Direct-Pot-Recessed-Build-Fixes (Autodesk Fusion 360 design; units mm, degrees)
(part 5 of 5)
sketch "Top installation slot for block nut (2)" plane through (-20, 0, 0) normal (1, 0, 0) x axis (0, 0, -1)
  line L1 (-53.5, -66.65) -> (-53.5, -73.35)
  line L2 (-59.1, -66.65) -> (-53.5, -66.65)
  line L3 (-59.1, -73.35) -> (-59.1, -66.65)
  line L4 (-53.5, -73.35) -> (-59.1, -73.35)
extrude "Extrude80" cut sketch "Top installation slot for block nut (2)" along normal blind 2.6
work_plane "WorkPlane1" AlongDistance -19.9 ExtraOffset 0
sketch "Crossblock captive M3 (-70, -1)" plane through (-19.9, 0, 0) normal (1, 0, 0) x axis (0, 0, -1)
  line L1 (-56.25, -68.4123) -> (-53.5, -66.8246)
  line L2 (-56.25, -71.5877) -> (-56.25, -68.4123)
  line L3 (-53.5, -73.1754) -> (-56.25, -71.5877)
  line L4 (-50.75, -71.5877) -> (-53.5, -73.1754)
  line L5 (-50.75, -68.4123) -> (-50.75, -71.5877)
  line L6 (-53.5, -66.8246) -> (-50.75, -68.4123)
extrude "Extrude1" new body sketch "Crossblock captive M3 (-70, -1)" along normal blind 2.4 bodies "HARDWARE Crossblock captive M3 (-70, -1)"
work_plane "WorkPlane2" AlongDistance -20 ExtraOffset 0
sketch "Thread envelope" plane through (-20, 0, 0) normal (1, 0, 0) x axis (0, 0, -1)
  circle C1 centre (-53.5, -70) radius 1.5
extrude "Extrude2" cut sketch "Thread envelope" along normal blind 2.6
work_plane "WorkPlane81" AlongDistance 15.3 ExtraOffset 0
sketch "Close mounting insert pilot (3)" plane through (15.3, 0, 0) normal (1, 0, 0) x axis (0, 0, -1)
  circle C1 centre (-53.5, -70) radius 2.01
extrude "Extrude81" add sketch "Close mounting insert pilot (3)" along normal blind 8.7
work_plane "WorkPlane82" AlongDistance 15.2 ExtraOffset 0
sketch "Block mount screw passage (3)" plane through (15.2, 0, 0) normal (1, 0, 0) x axis (0, 0, -1)
  circle C1 centre (-53.5, -70) radius 1.7
extrude "Extrude82" cut sketch "Block mount screw passage (3)" along normal blind 8.9
work_plane "WorkPlane83" AlongDistance 17.4 ExtraOffset 0
sketch "Crossblock captive hex nut (3)" plane through (17.4, 0, 0) normal (1, 0, 0) x axis (0, 0, -1)
  line L1 (-56.4, -68.3257) -> (-53.5, -66.6514)
  line L2 (-56.4, -71.6743) -> (-56.4, -68.3257)
  line L3 (-53.5, -73.3486) -> (-56.4, -71.6743)
  line L4 (-50.6, -71.6743) -> (-53.5, -73.3486)
  line L5 (-50.6, -68.3257) -> (-50.6, -71.6743)
  line L6 (-53.5, -66.6514) -> (-50.6, -68.3257)
extrude "Extrude83" cut sketch "Crossblock captive hex nut (3)" along normal blind 2.6
work_plane "WorkPlane84" AlongDistance 17.4 ExtraOffset 0
sketch "Top installation slot for block nut (3)" plane through (17.4, 0, 0) normal (1, 0, 0) x axis (0, 0, -1)
  line L1 (-53.5, -66.65) -> (-53.5, -73.35)
  line L2 (-59.1, -66.65) -> (-53.5, -66.65)
  line L3 (-59.1, -73.35) -> (-59.1, -66.65)
  line L4 (-53.5, -73.35) -> (-59.1, -73.35)
extrude "Extrude84" cut sketch "Top installation slot for block nut (3)" along normal blind 2.6
work_plane "WorkPlane1" AlongDistance 17.5 ExtraOffset 0
sketch "Crossblock captive M3 (-70, 1)" plane through (17.5, 0, 0) normal (1, 0, 0) x axis (0, 0, -1)
  line L1 (-56.25, -68.4123) -> (-53.5, -66.8246)
  line L2 (-56.25, -71.5877) -> (-56.25, -68.4123)
  line L3 (-53.5, -73.1754) -> (-56.25, -71.5877)
  line L4 (-50.75, -71.5877) -> (-53.5, -73.1754)
  line L5 (-50.75, -68.4123) -> (-50.75, -71.5877)
  line L6 (-53.5, -66.8246) -> (-50.75, -68.4123)
extrude "Extrude1" new body sketch "Crossblock captive M3 (-70, 1)" along normal blind 2.4 bodies "HARDWARE Crossblock captive M3 (-70, 1)"
work_plane "WorkPlane2" AlongDistance 17.4 ExtraOffset 0
sketch "Thread envelope" plane through (17.4, 0, 0) normal (1, 0, 0) x axis (0, 0, -1)
  circle C1 centre (-53.5, -70) radius 1.5
extrude "Extrude2" cut sketch "Thread envelope" along normal blind 2.6
work_plane "WorkPlane85" AlongDistance 8.6 ExtraOffset 0
sketch "Preload head first bridge relief" plane through (8.6, 0, 0) normal (1, 0, 0) x axis (0, 0, -1)
  line L1 (-54.8, -53.3) -> (-54.8, -56.7)
  line L2 (-55, -53.3) -> (-54.8, -53.3)
  line L3 (-55, -56.7) -> (-55, -53.3)
  line L4 (-54.8, -56.7) -> (-55, -56.7)
extrude "Extrude85" cut sketch "Preload head first bridge relief" along normal blind 6.8
work_plane "WorkPlane86" AlongDistance 10.3 ExtraOffset 0
sketch "Preload head crossed bridge relief" plane through (10.3, 0, 0) normal (1, 0, 0) x axis (0, 0, -1)
  line L1 (-54.6, -53.3) -> (-54.6, -56.7)
  line L2 (-54.8, -53.3) -> (-54.6, -53.3)
  line L3 (-54.8, -56.7) -> (-54.8, -53.3)
  line L4 (-54.6, -56.7) -> (-54.8, -56.7)
extrude "Extrude86" cut sketch "Preload head crossed bridge relief" along normal blind 3.4
work_plane "WorkPlane9" AlongDistance -9 ExtraOffset 0
sketch "Close sensor clamp insert pilot" plane through (0, -9, 0) normal (0, 1, 0) x axis (1, 0, 0)
  circle C1 centre (54.15, -73) radius 2.01
extrude "Extrude9" add sketch "Close sensor clamp insert pilot" along normal blind 8.9
work_plane "WorkPlane10" AlongDistance -9.1 ExtraOffset 0
sketch "Sensor clamp M3 clearance" plane through (0, -9.1, 0) normal (0, 1, 0) x axis (1, 0, 0)
  circle C1 centre (54.15, -73) radius 1.7
extrude "Extrude10" cut sketch "Sensor clamp M3 clearance" along normal blind 9.1
work_plane "WorkPlane11" AlongDistance -6.9 ExtraOffset 0
sketch "Sensor clamp captive hex nut" plane through (0, -6.9, 0) normal (0, 1, 0) x axis (1, 0, 0)
  line L1 (55.8243, -75.9) -> (57.4986, -73)
  line L2 (52.4757, -75.9) -> (55.8243, -75.9)
  line L3 (50.8014, -73) -> (52.4757, -75.9)
  line L4 (52.4757, -70.1) -> (50.8014, -73)
  line L5 (55.8243, -70.1) -> (52.4757, -70.1)
  line L6 (57.4986, -73) -> (55.8243, -70.1)
extrude "Extrude11" cut sketch "Sensor clamp captive hex nut" along normal blind 2.6
work_plane "WorkPlane12" AlongDistance 50.8 ExtraOffset 0
sketch "Clamp nut top installation slot" plane through (50.8, 0, 0) normal (1, 0, 0) x axis (0, 0, -1)
  line L1 (-73, -4.3) -> (-73, -6.9)
  line L2 (-78.1, -4.3) -> (-73, -4.3)
  line L3 (-78.1, -6.9) -> (-78.1, -4.3)
  line L4 (-73, -6.9) -> (-78.1, -6.9)
extrude "Extrude12" cut sketch "Clamp nut top installation slot" along normal blind 6.7
work_plane "WorkPlane1" AlongDistance -6.8 ExtraOffset 0
sketch "Sensor clamp captive M3 nut" plane through (0, -6.8, 0) normal (0, 1, 0) x axis (1, 0, 0)
  line L1 (55.7377, -75.75) -> (57.3254, -73)
  line L2 (52.5623, -75.75) -> (55.7377, -75.75)
  line L3 (50.9746, -73) -> (52.5623, -75.75)
  line L4 (52.5623, -70.25) -> (50.9746, -73)
  line L5 (55.7377, -70.25) -> (52.5623, -70.25)
  line L6 (57.3254, -73) -> (55.7377, -70.25)
extrude "Extrude1" new body sketch "Sensor clamp captive M3 nut" along normal blind 2.4 bodies "HARDWARE Sensor clamp captive M3 nut"
work_plane "WorkPlane2" AlongDistance -6.9 ExtraOffset 0
sketch "Thread envelope" plane through (0, -6.9, 0) normal (0, 1, 0) x axis (1, 0, 0)
  circle C1 centre (54.15, -73) radius 1.5
extrude "Extrude2" cut sketch "Thread envelope" along normal blind 2.6
work_plane "WorkPlane87" AlongDistance -24 ExtraOffset 0
sketch "Rear wall around captive block nuts" plane through (-24, 0, 0) normal (1, 0, 0) x axis (0, 0, -1)
  line L1 (-38, -73.9) -> (-38, -76)
  line L2 (-59, -73.9) -> (-38, -73.9)
  line L3 (-59, -76) -> (-59, -73.9)
  line L4 (-38, -76) -> (-59, -76)
extrude "Extrude87" add sketch "Rear wall around captive block nuts" along normal blind 48
work_plane "WorkPlane88" AlongDistance 1.1 ExtraOffset 0
sketch "Extend guide nut loading access through rear wall" plane through (1.1, 0, 0) normal (1, 0, 0) x axis (0, 0, -1)
  line L1 (-40.8, -73.8) -> (-40.8, -76.1)
  line L2 (-43.4, -73.8) -> (-40.8, -73.8)
  line L3 (-43.4, -76.1) -> (-43.4, -73.8)
  line L4 (-40.8, -76.1) -> (-43.4, -76.1)
extrude "Extrude88" cut sketch "Extend guide nut loading access through rear wall" along normal blind 5.8
work_plane "WorkPlane89" AlongDistance 17.1 ExtraOffset 0
sketch "Extend guide nut loading access through rear wall (1)" plane through (17.1, 0, 0) normal (1, 0, 0) x axis (0, 0, -1)
  line L1 (-40.8, -73.8) -> (-40.8, -76.1)
  line L2 (-43.4, -73.8) -> (-40.8, -73.8)
  line L3 (-43.4, -76.1) -> (-43.4, -73.8)
  line L4 (-40.8, -76.1) -> (-43.4, -76.1)
extrude "Extrude89" cut sketch "Extend guide nut loading access through rear wall (1)" along normal blind 5.8
work_plane "WorkPlane19" AlongDistance -34 ExtraOffset 0
sketch "Shaft cap nut captured by assembled halves" plane through (-34, 0, 0) normal (1, 0, 0) x axis (0, 0, -1)
  line L1 (-67.9, 1.6743) -> (-65, 3.3486)
  line L2 (-67.9, -1.6743) -> (-67.9, 1.6743)
  line L3 (-65, -3.3486) -> (-67.9, -1.6743)
  line L4 (-62.1, -1.6743) -> (-65, -3.3486)
  line L5 (-62.1, 1.6743) -> (-62.1, -1.6743)
  line L6 (-65, 3.3486) -> (-62.1, 1.6743)
extrude "Extrude19" cut sketch "Shaft cap nut captured by assembled halves" along normal blind 2.6
work_plane "WorkPlane1" AlongDistance -33.9 ExtraOffset 0
sketch "Shaft cap captured M3 nut" plane through (-33.9, 0, 0) normal (1, 0, 0) x axis (0, 0, -1)
  line L1 (-67.75, 1.5877) -> (-65, 3.1754)
  line L2 (-67.75, -1.5877) -> (-67.75, 1.5877)
  line L3 (-65, -3.1754) -> (-67.75, -1.5877)
  line L4 (-62.25, -1.5877) -> (-65, -3.1754)
  line L5 (-62.25, 1.5877) -> (-62.25, -1.5877)
  line L6 (-65, 3.1754) -> (-62.25, 1.5877)
extrude "Extrude1" new body sketch "Shaft cap captured M3 nut" along normal blind 2.4 bodies "HARDWARE Shaft cap captured M3 nut"
work_plane "WorkPlane2" AlongDistance -34 ExtraOffset 0
sketch "Thread envelope" plane through (-34, 0, 0) normal (1, 0, 0) x axis (0, 0, -1)
  circle C1 centre (-65, 0) radius 1.5
extrude "Extrude2" cut sketch "Thread envelope" along normal blind 2.6
work_plane "WorkPlane20" AlongDistance -4.5 ExtraOffset 0
sketch "Shaft joining captured nut" plane through (0, -4.5, 0) normal (0, 1, 0) x axis (1, 0, 0)
  line L1 (-13.3257, -67.9) -> (-11.6514, -65)
  line L2 (-16.6743, -67.9) -> (-13.3257, -67.9)
  line L3 (-18.3486, -65) -> (-16.6743, -67.9)
  line L4 (-16.6743, -62.1) -> (-18.3486, -65)
  line L5 (-13.3257, -62.1) -> (-16.6743, -62.1)
  line L6 (-11.6514, -65) -> (-13.3257, -62.1)
extrude "Extrude20" cut sketch "Shaft joining captured nut" along normal blind 2.6
work_plane "WorkPlane21" AlongDistance -18.35 ExtraOffset 0
sketch "Shaft nut loading slot from underside" plane through (-18.35, 0, 0) normal (1, 0, 0) x axis (0, 0, -1)
  line L1 (-56.9, -1.9) -> (-56.9, -4.5)
  line L2 (-65, -1.9) -> (-56.9, -1.9)
  line L3 (-65, -4.5) -> (-65, -1.9)
  line L4 (-56.9, -4.5) -> (-65, -4.5)
extrude "Extrude21" cut sketch "Shaft nut loading slot from underside" along normal blind 6.7
work_plane "WorkPlane22" AlongDistance -18.35 ExtraOffset 0
sketch "Shaft nut first anchored bridge relief" plane through (-18.35, 0, 0) normal (1, 0, 0) x axis (0, 0, -1)
  line L1 (-63.3, -4.5) -> (-63.3, -4.7)
  line L2 (-66.7, -4.5) -> (-63.3, -4.5)
  line L3 (-66.7, -4.7) -> (-66.7, -4.5)
  line L4 (-63.3, -4.7) -> (-66.7, -4.7)
extrude "Extrude22" cut sketch "Shaft nut first anchored bridge relief" along normal blind 6.7
work_plane "WorkPlane23" AlongDistance -16.7 ExtraOffset 0
sketch "Shaft nut crossed bridge relief" plane through (-16.7, 0, 0) normal (1, 0, 0) x axis (0, 0, -1)
  line L1 (-63.3, -4.7) -> (-63.3, -4.9)
  line L2 (-66.7, -4.7) -> (-63.3, -4.7)
  line L3 (-66.7, -4.9) -> (-66.7, -4.7)
  line L4 (-63.3, -4.9) -> (-66.7, -4.9)
extrude "Extrude23" cut sketch "Shaft nut crossed bridge relief" along normal blind 3.4
work_plane "WorkPlane1" AlongDistance -4.4 ExtraOffset 0
sketch "Shaft joining captured M3 nut -15" plane through (0, -4.4, 0) normal (0, 1, 0) x axis (1, 0, 0)
  line L1 (-13.4123, -67.75) -> (-11.8246, -65)
  line L2 (-16.5877, -67.75) -> (-13.4123, -67.75)
  line L3 (-18.1754, -65) -> (-16.5877, -67.75)
  line L4 (-16.5877, -62.25) -> (-18.1754, -65)
  line L5 (-13.4123, -62.25) -> (-16.5877, -62.25)
  line L6 (-11.8246, -65) -> (-13.4123, -62.25)
extrude "Extrude1" new body sketch "Shaft joining captured M3 nut -15" along normal blind 2.4 bodies "HARDWARE Shaft joining captured M3 nut -15"
work_plane "WorkPlane2" AlongDistance -4.5 ExtraOffset 0
sketch "Thread envelope" plane through (0, -4.5, 0) normal (0, 1, 0) x axis (1, 0, 0)
  circle C1 centre (-15, -65) radius 1.5
extrude "Extrude2" cut sketch "Thread envelope" along normal blind 2.6
work_plane "WorkPlane24" AlongDistance -4.5 ExtraOffset 0
sketch "Shaft joining captured nut (1)" plane through (0, -4.5, 0) normal (0, 1, 0) x axis (1, 0, 0)
  line L1 (16.6743, -67.9) -> (18.3486, -65)
  line L2 (13.3257, -67.9) -> (16.6743, -67.9)
  line L3 (11.6514, -65) -> (13.3257, -67.9)
  line L4 (13.3257, -62.1) -> (11.6514, -65)
  line L5 (16.6743, -62.1) -> (13.3257, -62.1)
  line L6 (18.3486, -65) -> (16.6743, -62.1)
extrude "Extrude24" cut sketch "Shaft joining captured nut (1)" along normal blind 2.6
work_plane "WorkPlane25" AlongDistance 11.65 ExtraOffset 0
sketch "Shaft nut loading slot from underside (1)" plane through (11.65, 0, 0) normal (1, 0, 0) x axis (0, 0, -1)
  line L1 (-56.9, -1.9) -> (-56.9, -4.5)
  line L2 (-65, -1.9) -> (-56.9, -1.9)
  line L3 (-65, -4.5) -> (-65, -1.9)
  line L4 (-56.9, -4.5) -> (-65, -4.5)
extrude "Extrude25" cut sketch "Shaft nut loading slot from underside (1)" along normal blind 6.7
work_plane "WorkPlane26" AlongDistance 11.65 ExtraOffset 0
sketch "Shaft nut first anchored bridge relief (1)" plane through (11.65, 0, 0) normal (1, 0, 0) x axis (0, 0, -1)
  line L1 (-63.3, -4.5) -> (-63.3, -4.7)
  line L2 (-66.7, -4.5) -> (-63.3, -4.5)
  line L3 (-66.7, -4.7) -> (-66.7, -4.5)
  line L4 (-63.3, -4.7) -> (-66.7, -4.7)
extrude "Extrude26" cut sketch "Shaft nut first anchored bridge relief (1)" along normal blind 6.7
work_plane "WorkPlane27" AlongDistance 13.3 ExtraOffset 0
sketch "Shaft nut crossed bridge relief (1)" plane through (13.3, 0, 0) normal (1, 0, 0) x axis (0, 0, -1)
  line L1 (-63.3, -4.7) -> (-63.3, -4.9)
  line L2 (-66.7, -4.7) -> (-63.3, -4.7)
  line L3 (-66.7, -4.9) -> (-66.7, -4.7)
  line L4 (-63.3, -4.9) -> (-66.7, -4.9)
extrude "Extrude27" cut sketch "Shaft nut crossed bridge relief (1)" along normal blind 3.4
work_plane "WorkPlane1" AlongDistance -4.4 ExtraOffset 0
sketch "Shaft joining captured M3 nut 15" plane through (0, -4.4, 0) normal (0, 1, 0) x axis (1, 0, 0)
  line L1 (16.5877, -67.75) -> (18.1754, -65)
  line L2 (13.4123, -67.75) -> (16.5877, -67.75)
  line L3 (11.8246, -65) -> (13.4123, -67.75)
  line L4 (13.4123, -62.25) -> (11.8246, -65)
  line L5 (16.5877, -62.25) -> (13.4123, -62.25)
  line L6 (18.1754, -65) -> (16.5877, -62.25)
extrude "Extrude1" new body sketch "Shaft joining captured M3 nut 15" along normal blind 2.4 bodies "HARDWARE Shaft joining captured M3 nut 15"
work_plane "WorkPlane2" AlongDistance -4.5 ExtraOffset 0
sketch "Thread envelope" plane through (0, -4.5, 0) normal (0, 1, 0) x axis (1, 0, 0)
  circle C1 centre (15, -65) radius 1.5
extrude "Extrude2" cut sketch "Thread envelope" along normal blind 2.6
work_plane "WorkPlane21" AlongDistance -7.1 ExtraOffset 0
sketch "Rear-loaded cam hex nut" plane through (-7.1, 0, 0) normal (1, 0, 0) x axis (0, 0, -1)
  line L1 (-42.4442, 27.1302) -> (-39.5442, 28.8045)
  line L2 (-42.4442, 23.7815) -> (-42.4442, 27.1302)
  line L3 (-39.5442, 22.1072) -> (-42.4442, 23.7815)
  line L4 (-36.6442, 23.7815) -> (-39.5442, 22.1072)
  line L5 (-36.6442, 27.1302) -> (-36.6442, 23.7815)
  line L6 (-39.5442, 28.8045) -> (-36.6442, 27.1302)
extrude "Extrude21" cut sketch "Rear-loaded cam hex nut" along normal blind 11.7
work_plane "WorkPlane1" AlongDistance 2.1 ExtraOffset 0
sketch "Cam captured M3 nut -45" plane through (2.1, 0, 0) normal (1, 0, 0) x axis (0, 0, -1)
  line L1 (-42.2942, 27.0436) -> (-39.5442, 28.6313)
  line L2 (-42.2942, 23.8681) -> (-42.2942, 27.0436)
  line L3 (-39.5442, 22.2804) -> (-42.2942, 23.8681)
  line L4 (-36.7942, 23.8681) -> (-39.5442, 22.2804)
  line L5 (-36.7942, 27.0436) -> (-36.7942, 23.8681)
  line L6 (-39.5442, 28.6313) -> (-36.7942, 27.0436)
extrude "Extrude1" new body sketch "Cam captured M3 nut -45" along normal blind 2.4 bodies "HARDWARE Cam captured M3 nut -45"
work_plane "WorkPlane2" AlongDistance 2 ExtraOffset 0
sketch "Thread envelope" plane through (2, 0, 0) normal (1, 0, 0) x axis (0, 0, -1)
  circle C1 centre (-39.5442, 25.4558) radius 1.5
extrude "Extrude2" cut sketch "Thread envelope" along normal blind 2.6
work_plane "WorkPlane22" AlongDistance -7.1 ExtraOffset 0
sketch "Rear-loaded cam hex nut (1)" plane through (-7.1, 0, 0) normal (1, 0, 0) x axis (0, 0, -1)
  line L1 (-31.9, 1.6743) -> (-29, 3.3486)
  line L2 (-31.9, -1.6743) -> (-31.9, 1.6743)
  line L3 (-29, -3.3486) -> (-31.9, -1.6743)
  line L4 (-26.1, -1.6743) -> (-29, -3.3486)
  line L5 (-26.1, 1.6743) -> (-26.1, -1.6743)
  line L6 (-29, 3.3486) -> (-26.1, 1.6743)
extrude "Extrude22" cut sketch "Rear-loaded cam hex nut (1)" along normal blind 11.7
work_plane "WorkPlane1" AlongDistance 2.1 ExtraOffset 0
sketch "Cam captured M3 nut 0" plane through (2.1, 0, 0) normal (1, 0, 0) x axis (0, 0, -1)
  line L1 (-31.75, 1.5877) -> (-29, 3.1754)
  line L2 (-31.75, -1.5877) -> (-31.75, 1.5877)
  line L3 (-29, -3.1754) -> (-31.75, -1.5877)
  line L4 (-26.25, -1.5877) -> (-29, -3.1754)
  line L5 (-26.25, 1.5877) -> (-26.25, -1.5877)
  line L6 (-29, 3.1754) -> (-26.25, 1.5877)
extrude "Extrude1" new body sketch "Cam captured M3 nut 0" along normal blind 2.4 bodies "HARDWARE Cam captured M3 nut 0"
work_plane "WorkPlane2" AlongDistance 2 ExtraOffset 0
sketch "Thread envelope" plane through (2, 0, 0) normal (1, 0, 0) x axis (0, 0, -1)
  circle C1 centre (-29, 0) radius 1.5
extrude "Extrude2" cut sketch "Thread envelope" along normal blind 2.6
work_plane "WorkPlane23" AlongDistance -7.1 ExtraOffset 0
sketch "Rear-loaded cam hex nut (2)" plane through (-7.1, 0, 0) normal (1, 0, 0) x axis (0, 0, -1)
  line L1 (-42.4442, -23.7815) -> (-39.5442, -22.1072)
  line L2 (-42.4442, -27.1302) -> (-42.4442, -23.7815)
  line L3 (-39.5442, -28.8045) -> (-42.4442, -27.1302)
  line L4 (-36.6442, -27.1302) -> (-39.5442, -28.8045)
  line L5 (-36.6442, -23.7815) -> (-36.6442, -27.1302)
  line L6 (-39.5442, -22.1072) -> (-36.6442, -23.7815)
extrude "Extrude23" cut sketch "Rear-loaded cam hex nut (2)" along normal blind 11.7
work_plane "WorkPlane1" AlongDistance 2.1 ExtraOffset 0
sketch "Cam captured M3 nut 45" plane through (2.1, 0, 0) normal (1, 0, 0) x axis (0, 0, -1)
  line L1 (-42.2942, -23.8681) -> (-39.5442, -22.2804)
  line L2 (-42.2942, -27.0436) -> (-42.2942, -23.8681)
  line L3 (-39.5442, -28.6313) -> (-42.2942, -27.0436)
  line L4 (-36.7942, -27.0436) -> (-39.5442, -28.6313)
  line L5 (-36.7942, -23.8681) -> (-36.7942, -27.0436)
  line L6 (-39.5442, -22.2804) -> (-36.7942, -23.8681)
extrude "Extrude1" new body sketch "Cam captured M3 nut 45" along normal blind 2.4 bodies "HARDWARE Cam captured M3 nut 45"
work_plane "WorkPlane2" AlongDistance 2 ExtraOffset 0
sketch "Thread envelope" plane through (2, 0, 0) normal (1, 0, 0) x axis (0, 0, -1)
  circle C1 centre (-39.5442, -25.4558) radius 1.5
extrude "Extrude2" cut sketch "Thread envelope" along normal blind 2.6
work_plane "WorkPlane24" AlongDistance 15.2 ExtraOffset 0
sketch "Rotor side-loaded clamp nut" plane through (0, 15.2, 0) normal (0, 1, 0) x axis (1, 0, 0)
  line L1 (1.6743, -67.9) -> (3.3486, -65)
  line L2 (-1.6743, -67.9) -> (1.6743, -67.9)
  line L3 (-3.3486, -65) -> (-1.6743, -67.9)
  line L4 (-1.6743, -62.1) -> (-3.3486, -65)
  line L5 (1.6743, -62.1) -> (-1.6743, -62.1)
  line L6 (3.3486, -65) -> (1.6743, -62.1)
extrude "Extrude24" cut sketch "Rotor side-loaded clamp nut" along normal blind 2.6
work_plane "WorkPlane25" AlongDistance -7.1 ExtraOffset 0
sketch "Rotor clamp nut insertion from back face" plane through (-7.1, 0, 0) normal (1, 0, 0) x axis (0, 0, -1)
  line L1 (-62.1, 17.8) -> (-62.1, 15.2)
  line L2 (-67.9, 17.8) -> (-62.1, 17.8)
  line L3 (-67.9, 15.2) -> (-67.9, 17.8)
  line L4 (-62.1, 15.2) -> (-67.9, 15.2)
extrude "Extrude25" cut sketch "Rotor clamp nut insertion from back face" along normal blind 7.1
work_plane "WorkPlane1" AlongDistance 15.3 ExtraOffset 0
sketch "Rotor clamp captured M3 nut" plane through (0, 15.3, 0) normal (0, 1, 0) x axis (1, 0, 0)
  line L1 (1.5877, -67.75) -> (3.1754, -65)
  line L2 (-1.5877, -67.75) -> (1.5877, -67.75)
  line L3 (-3.1754, -65) -> (-1.5877, -67.75)
  line L4 (-1.5877, -62.25) -> (-3.1754, -65)
  line L5 (1.5877, -62.25) -> (-1.5877, -62.25)
  line L6 (3.1754, -65) -> (1.5877, -62.25)
extrude "Extrude1" new body sketch "Rotor clamp captured M3 nut" along normal blind 2.4 bodies "HARDWARE Rotor clamp captured M3 nut"
work_plane "WorkPlane2" AlongDistance 15.2 ExtraOffset 0
sketch "Thread envelope" plane through (0, 15.2, 0) normal (0, 1, 0) x axis (1, 0, 0)
  circle C1 centre (0, -65) radius 1.5
extrude "Extrude2" cut sketch "Thread envelope" along normal blind 2.6
work_plane "WorkPlane7" AlongDistance 180 ExtraOffset 0
sketch "Small grip socket insert lead-in" plane through (0, 0, 180) normal (0, 0, 1) x axis (1, 0, 0)
  line L1 (-7.4, 1.9) -> (-7.4, 0)
  line L2 (-7.2, 2.1) -> (-7.4, 1.9)
  line L3 (-7.2, 0) -> (-7.2, 2.1)
  line L4 (-7.4, 0) -> (-7.2, 0)
  line L5 (-6.2, 0) -> (-8.4, 0)
revolve "Revolve2" sketch "Small grip socket insert lead-in" AlongAngle 360
work_plane "WorkPlane8" AlongDistance 190 ExtraOffset 0
sketch "Small grip socket insert lead-in (1)" plane through (0, 0, 190) normal (0, 0, 1) x axis (1, 0, 0)
  line L1 (-7.4, 1.9) -> (-7.4, 0)
  line L2 (-7.2, 2.1) -> (-7.4, 1.9)
  line L3 (-7.2, 0) -> (-7.2, 2.1)
  line L4 (-7.4, 0) -> (-7.2, 0)
  line L5 (-6.2, 0) -> (-8.4, 0)
revolve "Revolve3" sketch "Small grip socket insert lead-in (1)" AlongAngle 360
ground "Pin164"
ground "Pin165"
ground "Pin166"
ground "Pin167"
ground "Pin168"
ground "Pin169"
ground "Pin170"
ground "Pin171"
ground "Pin172"
ground "Pin173"
ground "Pin174"
ground "Pin175"
ground "Pin176"
ground "Pin177"
ground "Pin178"
ground "Pin179"
ground "Pin180"
ground "Pin181"
ground "Pin182"
ground "Pin183"
ground "Pin184"
ground "Pin185"
ground "Pin186"
ground "Pin187"
ground "Pin188"
ground "Pin189"
ground "Pin190"
ground "Pin191"
ground "Pin192"
ground "Pin193"
ground "Pin194"
ground "Pin195"
ground "Pin196"
ground "Pin197"
ground "Pin198"
ground "Pin199"
ground "Pin200"
ground "Pin201"
ground "Pin202"
ground "Pin203"
ground "Pin204"
ground "Pin205"
ground "Pin206"
ground "Pin207"
ground "Pin208"
ground "Pin209"
ground "Pin210"
ground "Pin211"
ground "Pin212"
ground "Pin213"
ground "Pin214"
ground "Pin215"
ground "Pin216"
ground "Pin217"
ground "Pin218"
ground "Pin219"
ground "Pin220"
ground "Pin221"
ground "Pin222"
ground "Pin223"
ground "Pin224"
ground "Pin225"
ground "Pin226"
ground "Pin227"
ground "Pin228"
ground "Pin229"
ground "Pin230"
ground "Pin231"
ground "Pin232"
ground "Pin233"
ground "Pin234"
ground "Pin235"
ground "Pin236"
ground "Pin237"
ground "Pin238"
ground "Pin239"
ground "Pin240"
ground "Pin241"
ground "Pin242"
ground "Pin243"
ground "Pin244"
ground "Pin245"
ground "Unpin246"
ground "Unpin247"
ground "Unpin248"
ground "Unpin249"
ground "Unpin250"
ground "Unpin251"
ground "Unpin252"
ground "Unpin253"
ground "Unpin254"
ground "Unpin255"
ground "Unpin256"
ground "Unpin257"
ground "Unpin258"
ground "Unpin259"
ground "Unpin260"
ground "Unpin261"
ground "Unpin262"
ground "Unpin263"
ground "Unpin264"
ground "Unpin265"
ground "Unpin266"
ground "Unpin267"
ground "Unpin268"
ground "Unpin269"
ground "Unpin270"
ground "Unpin271"
ground "Unpin272"
ground "Unpin273"
ground "Unpin274"
ground "Unpin275"
ground "Unpin276"
ground "Unpin277"
ground "Unpin278"
ground "Unpin279"
ground "Unpin280"
ground "Unpin281"
ground "Unpin282"
ground "Unpin283"
ground "Unpin284"
ground "Unpin285"
ground "Unpin286"
ground "Unpin287"
ground "Unpin288"
ground "Unpin289"
ground "Unpin290"
ground "Unpin291"
ground "Unpin292"
ground "Unpin293"
ground "Unpin294"
ground "Unpin295"
ground "Unpin296"
ground "Unpin297"
ground "Unpin298"
ground "Unpin299"
ground "Unpin300"
ground "Unpin301"
ground "Unpin302"
ground "Unpin303"
ground "Unpin304"
ground "Unpin305"
ground "Unpin306"
ground "Unpin307"
ground "Unpin308"
ground "Unpin309"
ground "Unpin310"
ground "Unpin311"
ground "Unpin312"
ground "Unpin313"
ground "Unpin314"
ground "Unpin315"
ground "Unpin316"
ground "Unpin317"
ground "Unpin318"
ground "Unpin319"
ground "Unpin320"
ground "Unpin321"
ground "Unpin322"
ground "Unpin323"
ground "Unpin324"
ground "Unpin325"
ground "Unpin326"
ground "Unpin327"
position "Position1"
ground "Pin328"
ground "Pin329"
ground "Pin330"
ground "Pin331"
ground "Pin332"
ground "Pin333"
ground "Pin334"
ground "Pin335"
ground "Pin336"
ground "Pin337"
ground "Pin338"
ground "Pin339"
ground "Pin340"
ground "Pin341"
ground "Pin342"
ground "Pin343"
ground "Pin344"
ground "Pin345"
ground "Pin346"
ground "Pin347"
ground "Pin348"
ground "Pin349"
ground "Pin350"
ground "Pin351"
ground "Pin352"
ground "Pin353"
ground "Pin354"
ground "Pin355"
ground "Pin356"
ground "Pin357"
ground "Pin358"
ground "Pin359"
ground "Pin360"
ground "Pin361"
ground "Pin362"
ground "Pin363"
ground "Pin364"
ground "Pin365"
ground "Pin366"
ground "Pin367"
ground "Pin368"
ground "Pin369"
ground "Pin370"
ground "Pin371"
ground "Pin372"
ground "Pin373"
ground "Pin374"
ground "Pin375"
ground "Pin376"
ground "Pin377"
ground "Pin378"
ground "Pin379"
ground "Pin380"
ground "Pin381"
ground "Pin382"
ground "Pin383"
ground "Pin384"
ground "Pin385"
ground "Pin386"
ground "Pin387"
ground "Pin388"
ground "Pin389"
ground "Pin390"
ground "Pin391"
ground "Pin392"
ground "Pin393"
ground "Pin394"
ground "Pin395"
ground "Pin396"
ground "Pin397"
ground "Pin398"
ground "Pin399"
ground "Pin400"
ground "Pin401"
ground "Pin402"
ground "Pin403"
ground "Pin404"
ground "Pin405"
ground "Pin406"
ground "Pin407"
ground "Pin408"
ground "Pin409"
work_plane "WorkPlane85" AlongDistance 57.9 ExtraOffset 0
sketch "Trim former insert fill flush with carriage face" plane through (57.9, 0, 0) normal (1, 0, 0) x axis (0, 0, -1)
  line L1 (-62.9, -28) -> (-62.9, -28.2)
  line L2 (-67.1, -28) -> (-62.9, -28)
  line L3 (-67.1, -28.2) -> (-67.1, -28)
  line L4 (-62.9, -28.2) -> (-67.1, -28.2)
extrude "Extrude85" cut sketch "Trim former insert fill flush with carriage face" along normal blind 4.5
work_plane "WorkPlane86" AlongDistance 57.9 ExtraOffset 0
sketch "Trim former insert fill flush with carriage face (1)" plane through (57.9, 0, 0) normal (1, 0, 0) x axis (0, 0, -1)
  line L1 (-62.9, 28.2) -> (-62.9, 28)
  line L2 (-67.1, 28.2) -> (-62.9, 28.2)
  line L3 (-67.1, 28) -> (-67.1, 28.2)
  line L4 (-62.9, 28) -> (-67.1, 28)
extrude "Extrude86" cut sketch "Trim former insert fill flush with carriage face (1)" along normal blind 4.5
ground "Unpin410"
ground "Unpin411"
ground "Unpin412"
ground "Unpin413"
ground "Unpin414"
ground "Unpin415"
ground "Unpin416"
ground "Unpin417"
ground "Unpin418"
ground "Unpin419"
ground "Unpin420"
ground "Unpin421"
ground "Unpin422"
ground "Unpin423"
ground "Unpin424"
ground "Unpin425"
ground "Unpin426"
ground "Unpin427"
ground "Unpin428"
ground "Unpin429"
ground "Unpin430"
ground "Unpin431"
ground "Unpin432"
ground "Unpin433"
ground "Unpin434"
ground "Unpin435"
ground "Unpin436"
ground "Unpin437"
ground "Unpin438"
ground "Unpin439"
ground "Unpin440"
ground "Unpin441"
ground "Unpin442"
as_built_joint "As-built15"
as_built_joint "As-built16"
as_built_joint "As-built17" RotateMinimum -52 RotateMaximum 52
as_built_joint "As-built18" RotateMinimum -6 RotateMaximum 1
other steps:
create_component "CreateComponent1"
create_component "CreateComponent2"
create_component "CreateComponent3"
create_component "CreateComponent4"
create_component "CreateComponent5"
create_component "CreateComponent6"
create_component "CreateComponent7"
create_component "CreateComponent8"
create_component "CreateComponent9"
create_component "CreateComponent10"
create_component "CreateComponent11"
create_component "CreateComponent12"
create_component "CreateComponent13"
create_component "CreateComponent14"
create_component "CreateComponent16"
create_component "CreateComponent28"
create_component "CreateComponent29"
create_component "CreateComponent49"
create_component "CreateComponent89"
create_component "CreateComponent90"
create_component "CreateComponent140"
create_component "CreateComponent141"
create_component "CreateComponent142"
create_component "CreateComponent143"
create_component "CreateComponent144"
create_component "CreateComponent145"
create_component "CreateComponent146"
create_component "CreateComponent147"
create_component "CreateComponent148"
create_component "CreateComponent149"
create_component "CreateComponent150"
create_component "CreateComponent151"
create_component "CreateComponent152"
create_component "CreateComponent153"
create_component "CreateComponent154"
create_component "CreateComponent155"
create_component "CreateComponent156"
create_component "CreateComponent157"
create_component "CreateComponent158"
create_component "CreateComponent159"
create_component "CreateComponent160"
create_component "CreateComponent161"
create_component "CreateComponent162"
create_component "CreateComponent163"
create_component "CreateComponent164"
create_component "CreateComponent165"
create_component "CreateComponent166"
create_component "CreateComponent167"
create_component "CreateComponent171"
create_component "CreateComponent172"
create_component "CreateComponent173"
create_component "CreateComponent174"
create_component "CreateComponent175"
create_component "CreateComponent176"
create_component "CreateComponent177"
create_component "CreateComponent178"
create_component "CreateComponent179"
create_component "CreateComponent180"
create_component "CreateComponent181"
create_component "CreateComponent182"
create_component "CreateComponent183"
create_component "CreateComponent184"
create_component "CreateComponent185"
create_component "CreateComponent186"
create_component "CreateComponent187"
create_component "CreateComponent188"
create_component "CreateComponent189"
create_component "CreateComponent190"
create_component "CreateComponent191"
create_component "CreateComponent192"
create_component "CreateComponent193"
create_component "CreateComponent194"
create_component "CreateComponent195"
create_component "CreateComponent196"
create_component "CreateComponent197"
create_component "CreateComponent198"
create_component "CreateComponent199"
create_component "CreateComponent200"
create_component "CreateComponent201"
create_component "CreateComponent202"
create_component "CreateComponent203"
create_component "CreateComponent204"
named bodies: "P01 Left rail sideplate", "P02 Right rail sideplate", "P03 Left flanged journal bush", "P04 Right bush lower half", "P05 Shaft lower half", "P06 Shaft retaining cap", "P07 Integral lever rotor and cam carrier", "P08 Cam 7 gates - stable endpoints", "P08 Cam 5 gates - stable endpoints", "P08 Cam 3 gates - stable endpoints", "P09 Grip insert half", "P10 Grip screw half", "P11 Forked roller follower", "P13 Spring reaction crossblock", "P21 Follower left axial spacer", "P22 Follower right axial spacer", "HARDWARE Roller axle M3 nut", "P23 Left rotor thrust spacer", "P24 Right rotor thrust spacer", "HARDWARE Rail M5x14 DIN912 (-30, -1)", "HARDWARE Rail M5x14 DIN912 (-30, 1)", "HARDWARE Rail M5x14 DIN912 (30, -1)", "HARDWARE Rail M5x14 DIN912 (30, 1)", "P25 Captured printed pivot lower half", "P26 Captured printed pivot upper half", "HARDWARE Grip M3x20 cap head 180", "HARDWARE Grip M3x20 cap head 190", "HARDWARE Stop M3x20 cap head -1", "HARDWARE Stop M3 plain captive nut -1", "HARDWARE Stop M3x20 cap head 1", "HARDWARE Stop M3 plain captive nut 1", "HARDWARE 623ZZ roller bearing at 8", "HARDWARE 623ZZ roller bearing at 12", "P27 Printed guide sleeve 4", "HARDWARE Cup guide M3x12 4", "P27 Printed guide sleeve 20", "HARDWARE Cup guide M3x12 20", "P14 Captive spring cup for 9 mm spring", "P15 Recessed preload limit collar 1 mm", "HARDWARE Preload M3x20 cap head", "REFERENCE Stock spring OD9 wire1 free20 - rate and solid height assumed", "P16 Compact adjustable RK097 mount", "HARDWARE Compact carriage M3x12 -1", "HARDWARE Compact carriage M3x12 1", "P18 Compact floating coupling disc", "P19 Compact one-piece sensor clamp", "HARDWARE Compact sensor clamp M3x16", "HARDWARE Shaft joining M3x8 -15", "HARDWARE Shaft joining M3x8 15", "P28 Shaft alignment key -5", "P28 Shaft alignment key 5", "P05 Shaft upper half", "HARDWARE Main shaft cap M3x8 cap head", "HARDWARE Cam M3x10 cap head -45", "HARDWARE Cam M3x10 cap head 0", "HARDWARE Cam M3x10 cap head 45", "HARDWARE Roller axle M3x20 cap head", "HARDWARE Crossblock M3x20 cap head (-62, -1)", "HARDWARE Crossblock M3x20 cap head (-62, 1)", "HARDWARE Crossblock M3x20 cap head (-70, -1)"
